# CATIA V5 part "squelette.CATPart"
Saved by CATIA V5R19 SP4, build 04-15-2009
Part number: Squelette
Publications: "Point.3", "Point.4", "Point.5", "Point.6", "Plan.1", "Plan.2", "Plan.3", "Plan.4", "Point.7", "Plan.5", "Point.8", "Plan.6", "Point.9", "Plan.7", "Point.10", "Droite.3", "Point.12", "Point.13", "Point.16", "Droite.4", "Droite.5", "Point.17", "Plan.8", "Point.1", "Plan.9", "Point.19", "Plan.10", "Point.20", "Plan.11", "Plan.12", "Point.21", "Plan.13", "Droite.1", "Plan.16", "Point.24", "Plan.17", "Point.25", "Point.26", "Plan.18", "Point.27", "Plan.19", "Point.28", "Plan.20", "Point.29", "Plan.21", "Point.31", "Plan.23", "Point.32", "Plan.24", "Point.33", "Plan.25", "Point.34", "Plan.26", "Point.2", "Point.35", "Plan.27", "Plan.28", "Plan.29", "Point.37", "Plan.31", "Point.38", "Plan.32", "Droite.7"
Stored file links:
  G:\EU_thinkMotion\CFAO_2010\SIL_groupe2\SIL_groupe2\msauret\Brevet_Sauret_parametre\squelette.CATPart

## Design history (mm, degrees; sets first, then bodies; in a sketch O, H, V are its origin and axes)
Set1
  Point1: (0, 0, 0)
  Line1: type PtDir, RefPoint Point1, Direction yz-plane, Start 0, End 20
  Plane1: type OffsetPt, RefPlane yz-plane, RefPoint Point4
  Point2: (185, 0, 80)
  Line2: type PtDir, RefPoint Point2, Direction Line1, Start 0, End 20
  Plane2: type OffsetPt, RefPlane yz-plane, RefPoint Point3
  Point3: (4, 0, 0)
  Point4: (163, 0, 0)
  Point5: (167, 0, 0)
  Point6: (183, 0, 0)
  Plane3: type OffsetPt, RefPlane yz-plane, RefPoint Point5
  Plane4: type OffsetPt, RefPlane yz-plane, RefPoint Point6
  Point7: (168, 0, 0)
  Plane5: type OffsetPt, RefPlane yz-plane, RefPoint Point7
  Point8: (172, 0, 0)
  Plane6: type OffsetPt, RefPlane yz-plane, RefPoint Point8
  Point9: (158, 0, 0)
  Plane7: type OffsetPt, RefPlane yz-plane, RefPoint Point9
  Point10: (158, 0, 35)
  Line3: type PtDir, RefPoint Point10, Direction Line1, Start -25, End 25
  Point11: (158, 30.3109, -17.5)
  Point12: (158, -30.311, -17.5)
  Point13: (158, 30.3109, -17.5)
  Line4: type PtDir, RefPoint Point13, Direction Line1, Start -25, End 25
  Line5: type PtDir, RefPoint Point12, Direction Line1, Start -25, End 25
  Point14: (152, 0, 0)
  Plane8: type OffsetPt, RefPlane yz-plane, RefPoint Point14
  Plane9: type OffsetPt, RefPlane yz-plane, RefPoint Point1
  Point15: (164, 0, 0)
  Plane10: type OffsetPt, RefPlane yz-plane, RefPoint Point15
  Point16: (8, 0, 0)
  Plane11: type OffsetPt, RefPlane yz-plane, RefPoint Point16
  Point17: (159, 0, 0)
  Plane12: type OffsetPt, RefPlane yz-plane, RefPoint Point17
  Plane13: type OffsetPt, RefPlane xy-plane, RefPoint Point4
  Point18: (182, 0, 0)
  Plane14: type OffsetPt, RefPlane yz-plane, RefPoint Point18
  Point19: (185, 0, 0)
  Plane15: type OffsetPt, RefPlane yz-plane, RefPoint Point19
  Point20: (17, 0, 0)
  Plane16: type OffsetPt, RefPlane yz-plane, RefPoint Point20
  Point21: (21, 0, 0)
  Plane17: type OffsetPt, RefPlane yz-plane, RefPoint Point21
  Point22: (148, 0, 0)
  Plane18: type OffsetPt, RefPlane yz-plane, RefPoint Point22
  Point23: (154, 0, 0)
  Plane19: type OffsetPt, RefPlane yz-plane, RefPoint Point23
  Point24: (205, 0, 0)
  Plane20: type OffsetPt, RefPlane yz-plane, RefPoint Point24
  Point25: (183, 0, 0)
  Plane21: type OffsetPt, RefPlane yz-plane, RefPoint Point25
  Point26: (173, 0, 0)
  Plane22: type OffsetPt, RefPlane yz-plane, RefPoint Point26
  Point27: (160, 0, 0)
  Plane23: type OffsetPt, RefPlane yz-plane, RefPoint Point27
  Point28: (215, 0, 80)
  Plane24: type OffsetPt, RefPlane yz-plane, RefPoint Point28
  Plane25: type OffsetPt, RefPlane zx-plane, RefPoint Point2
  Plane26: type OffsetPt, RefPlane yz-plane, RefPoint Point2
  Point29: (190, 0, 0)
  Plane27: type OffsetPt, RefPlane yz-plane, RefPoint Point29
  Point30: (0, 0, 124)
  Plane28: type OffsetPt, RefPlane xy-plane, RefPoint Point30
  Line6: type PtPt, FirstPoint Point30, SecondPoint Point1
Body1 (main body)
